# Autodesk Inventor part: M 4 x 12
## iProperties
IsCustomPart: 0
Created: 2009-02
Part Number: M 4 x 12
Material: 강, 연강
Description: 6각머리 태핑 나사
Document SubType Name: Modeling
Standard: KS B 1003
Designer: KYOUNG IL JANG
Standards Organization: KS
Language: ko-KR
Size Designation: M 4 x 12
Categories: <MemberInstance><Categories><Category DisplayName="조임쇠" InternalName="e4da775c-781d-43d5-af7c-5136215cf5a6" Mnemonic="FSTN"><Category DisplayName="볼트" InternalN
Density: 7.86 g/cm^3
Mass: 2.23465 g
Surface Area: 3.30853 cm^2
Volume: 0.284306 cm^3
Author: KYOUNG IL JANG
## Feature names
1. Fillet2
